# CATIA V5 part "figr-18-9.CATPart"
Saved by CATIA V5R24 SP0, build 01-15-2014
Part number: Part1
Bounding box of the stored display mesh (mm): x -125 to 125, y -70.235 to 70.235, z 0 to 30
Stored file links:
  D:\KAVITA\CATIA V5-6R2014 Project_ Kavita\CATIA V5-6R2014_partfiles\Partfiles\c17_caia_v6-6r2014_prt\figr-17-8.CATPart
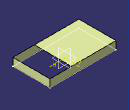
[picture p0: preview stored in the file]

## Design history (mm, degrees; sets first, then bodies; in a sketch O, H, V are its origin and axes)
Body1 (main body)
  Sketch1 on xy-plane, origin (0, 0, 0), H (1, 0, 0), V (0, 1, 0)
    line L1 (125, 70.235) -> (125, -70.235)
    line L2 (125, -70.235) -> (-125, -70.235)
    line L3 (-125, -70.235) -> (-125, 70.235)
    line L4 (-125, 70.235) -> (125, 70.235)
    length L2 = 250
    length L3 = 140.47
    vertical: L1 V, L3 V
    horizontal: L2 H, L4 H
    equidistance: L1 L3 O, L2 L4 O
  Extrude1: Lim1 30, Lim2 0, Element1 Sketch1
  DatumSurface1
